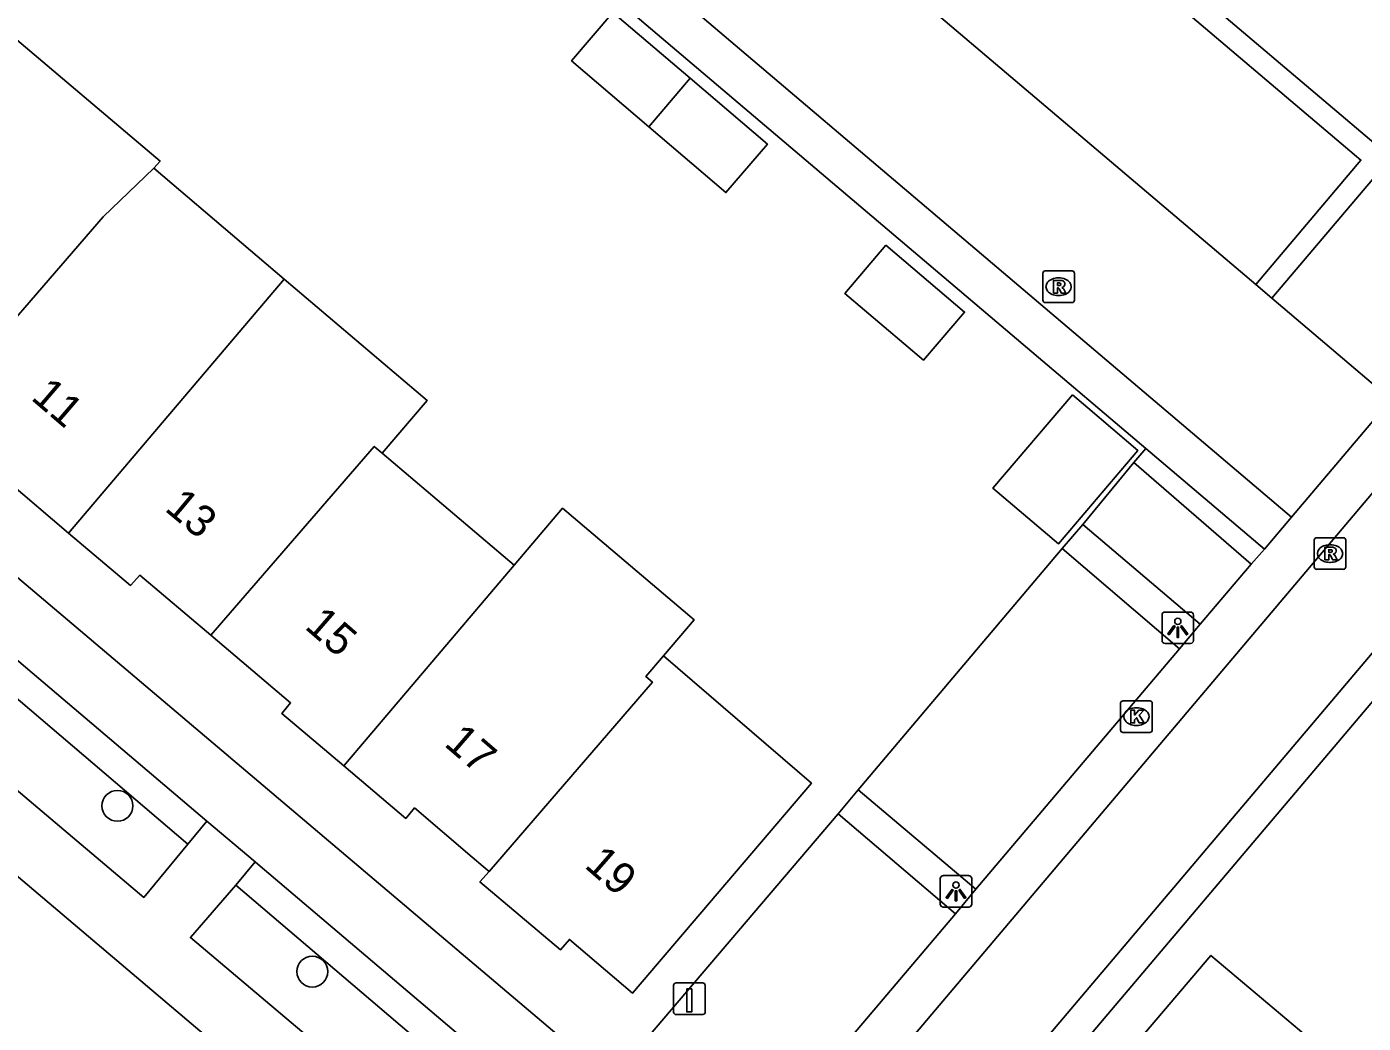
# Model space of a CAD drawing. Extents: x 156414 to 157775, y 382335 to 383765.
# Drawn here: x 156887.69 to 156930, y 382464.58 to 382496.14 of the extents above; entities that cross this region are included whole.
import ezdxf

# ---------------------------------------------------------------- set-up
doc = ezdxf.new("R2010")
doc.units = 0
for name, color, linetype in [('IMGEO_Boom', 7, 'Continuous'), ('IMGEO_Haag', 7, 'Continuous'), ('IMGEO_Kolk', 7, 'Continuous'), ('IMGEO_Laadpaal', 7, 'Continuous'), ('IMGEO_Lichtpunt', 7, 'Continuous'), ('IMGEO_Pand', 7, 'Continuous'), ('IMGEO_Pand_nummerreeks', 7, 'Continuous'), ('IMGEO_Parkeervlak_open', 7, 'Continuous'), ('IMGEO_Rijbaan_lokaal_halfverhard', 7, 'Continuous'), ('IMGEO_Rijbaan_lokaal_open', 7, 'Continuous'), ('IMGEO_Rioolput', 7, 'Continuous'), ('IMGEO_Voetpad_open', 7, 'Continuous')]:
    doc.layers.add(name, color=color, linetype=linetype)

msp = doc.modelspace()

# ---------------------------------------------------------------- linework, layer by layer
at = {"layer": 'IMGEO_Boom'}
for centre in [(156890.565, 382471.468), (156896.734, 382466.219)]:
    msp.add_circle(centre, 0.489, dxfattribs=at)
at = {"layer": 'IMGEO_Haag'}
for points in [[(156917.74, 382502.264), (156929.928, 382491.915), (156926.602, 382487.977)], [(156865.838, 382490.195), (156867.222, 382492.051), (156892.793, 382470.251)], [(156923.115, 382482.783), (156922.744, 382482.335)], [(156920.474, 382479.614), (156921.12, 382480.379)], [(156914.017, 382471.975), (156913.377, 382471.218)], [(156894.312, 382468.956), (156904.355, 382460.394), (156902.914, 382458.82)]]:
    msp.add_lwpolyline(points, dxfattribs=at)
at = {"layer": 'IMGEO_Kolk'}
for p, q in [((156922.32, 382473.867), (156922.32, 382474.719)), ((156922.395, 382474.793), (156923.247, 382474.793)), ((156922.808, 382474.573), (156922.833, 382474.573)), ((156923.321, 382474.719), (156923.321, 382473.867)), ((156923.247, 382473.793), (156922.395, 382473.793)), ((156922.831, 382474.013), (156922.806, 382474.013))]:
    msp.add_line(p, q, dxfattribs=at)
for points in [[(156922.32, 382473.867), (156922.32, 382474.719)], [(156922.395, 382474.793), (156923.247, 382474.793)], [(156923.321, 382474.719), (156923.321, 382473.867)], [(156922.641, 382474.493), (156922.764, 382474.493), (156922.764, 382474.342), (156922.894, 382474.493), (156923.058, 382474.493), (156922.912, 382474.342), (156923.065, 382474.093), (156922.913, 382474.093), (156922.828, 382474.257), (156922.764, 382474.19), (156922.764, 382474.093), (156922.641, 382474.093), (156922.641, 382474.493)], [(156923.247, 382473.793), (156922.395, 382473.793)]]:
    msp.add_lwpolyline(points, dxfattribs=at)
for centre, start, end in [((156922.397, 382474.717), 91.552, 178.448), ((156922.397, 382474.717), 91.552, 178.448), ((156923.245, 382474.717), 1.552, 88.448), ((156923.245, 382474.717), 1.552, 88.448), ((156922.397, 382473.869), 181.552, 268.448), ((156922.397, 382473.869), 181.552, 268.448), ((156923.245, 382473.869), 271.552, 358.448), ((156923.245, 382473.869), 271.552, 358.448)]:
    msp.add_arc(centre, 0.0765, start, end, dxfattribs=at)
for centre, major_axis, ratio, start_param, end_param in [((156922.807, 382474.293), (-0.387, 0.002), 0.722429, 4.712389, 7.853982), ((156922.832, 382474.293), (-0.39, 0.002), 0.717154, 1.570796, 4.712389)]:
    msp.add_ellipse(centre, major_axis=major_axis, ratio=ratio, start_param=start_param, end_param=end_param, dxfattribs=at)
at = {"layer": 'IMGEO_Laadpaal'}
for p, q in [((156908.172, 382465.775), (156908.172, 382464.934)), ((156908.172, 382465.775), (156908.172, 382464.934)), ((156909.088, 382465.859), (156908.247, 382465.859)), ((156909.088, 382465.859), (156908.247, 382465.859)), ((156909.172, 382464.943), (156909.172, 382465.784)), ((156909.172, 382464.943), (156909.172, 382465.784)), ((156908.256, 382464.859), (156909.097, 382464.859)), ((156908.256, 382464.859), (156909.097, 382464.859))]:
    msp.add_line(p, q, dxfattribs=at)
msp.add_lwpolyline([(156908.587, 382465.672), (156908.747, 382465.672), (156908.747, 382464.939), (156908.587, 382464.939), (156908.587, 382465.672)], dxfattribs=at)
for centre, start, end in [((156908.25, 382465.781), 92.4484, 184.2845), ((156908.25, 382465.781), 92.4484, 184.2845), ((156909.094, 382465.781), 2.4484, 94.2845), ((156909.094, 382465.781), 2.4484, 94.2845), ((156908.25, 382464.937), 182.4484, 274.2845), ((156908.25, 382464.937), 182.4484, 274.2845), ((156909.094, 382464.937), 272.4484, 4.2845), ((156909.094, 382464.937), 272.4484, 4.2845)]:
    msp.add_arc(centre, 0.0779, start, end, dxfattribs=at)
at = {"layer": 'IMGEO_Lichtpunt'}
for p, q in [((156923.633, 382477.509), (156923.633, 382476.702)), ((156923.633, 382477.509), (156923.633, 382476.702)), ((156924.535, 382477.604), (156923.727, 382477.604)), ((156924.535, 382477.604), (156923.727, 382477.604)), ((156924.629, 382476.702), (156924.629, 382477.509)), ((156924.629, 382476.702), (156924.629, 382477.509)), ((156923.727, 382476.608), (156924.535, 382476.608)), ((156923.727, 382476.608), (156924.535, 382476.608)), ((156916.611, 382469.161), (156916.611, 382468.354)), ((156916.611, 382469.161), (156916.611, 382468.354)), ((156917.513, 382469.256), (156916.705, 382469.256)), ((156917.513, 382469.256), (156916.705, 382469.256)), ((156917.607, 382468.354), (156917.607, 382469.161)), ((156917.607, 382468.354), (156917.607, 382469.161)), ((156916.705, 382468.26), (156917.513, 382468.26)), ((156916.705, 382468.26), (156917.513, 382468.26))]:
    msp.add_line(p, q, dxfattribs=at)
for points in [[(156924.007, 382477.173), (156924.046, 382477.145), (156923.858, 382476.883), (156923.82, 382476.91), (156924.007, 382477.173)], [(156924.109, 382477.125), (156924.156, 382477.125), (156924.156, 382476.803), (156924.109, 382476.803), (156924.109, 382477.125)], [(156924.219, 382477.145), (156924.257, 382477.172), (156924.444, 382476.91), (156924.405, 382476.882), (156924.219, 382477.145)], [(156916.985, 382468.825), (156917.024, 382468.797), (156916.836, 382468.535), (156916.798, 382468.562), (156916.985, 382468.825)], [(156917.087, 382468.777), (156917.134, 382468.777), (156917.134, 382468.455), (156917.087, 382468.455), (156917.087, 382468.777)], [(156917.197, 382468.797), (156917.235, 382468.824), (156917.422, 382468.562), (156917.383, 382468.534), (156917.197, 382468.797)]]:
    msp.add_lwpolyline(points, dxfattribs=at)
for centre in [(156924.132, 382477.307), (156917.11, 382468.959)]:
    msp.add_circle(centre, 0.0994, dxfattribs=at)
for centre, start, end in [((156923.727, 382477.509), 90, 180), ((156923.727, 382477.509), 90, 180), ((156924.535, 382477.509), 0, 90), ((156924.535, 382477.509), 0, 90), ((156923.727, 382476.702), 180, 270), ((156923.727, 382476.702), 180, 270), ((156924.535, 382476.702), 270, 0), ((156924.535, 382476.702), 270, 360), ((156916.705, 382469.161), 90, 180), ((156916.705, 382469.161), 90, 180), ((156917.513, 382469.161), 0, 90), ((156917.513, 382469.161), 0, 90), ((156916.705, 382468.354), 180, 270), ((156916.705, 382468.354), 180, 270), ((156917.513, 382468.354), 270, 0), ((156917.513, 382468.354), 270, 360)]:
    msp.add_arc(centre, 0.0946, start, end, dxfattribs=at)
at = {"layer": 'IMGEO_Pand'}
for points in [[(156907.385, 382492.974), (156904.941, 382495.062), (156906.25, 382496.595), (156908.694, 382494.507)], [(156885.573, 382493.956), (156887.239, 382495.838), (156891.913, 382491.884), (156891.713, 382491.658)], [(156908.694, 382494.507), (156911.138, 382492.42), (156909.829, 382490.887), (156907.385, 382492.974)], [(156907.385, 382492.974), (156908.694, 382494.507)], [(156891.713, 382491.658), (156890.113, 382490.118), (156884.943, 382484.14)], [(156891.713, 382491.658), (156895.841, 382488.151)], [(156914.894, 382489.224), (156917.381, 382487.106), (156916.078, 382485.576), (156913.591, 382487.694), (156914.894, 382489.224)], [(156889.019, 382480.107), (156895.841, 382488.151)], [(156895.841, 382488.151), (156900.374, 382484.301), (156898.946, 382482.636)], [(156920.8, 382484.482), (156921.286, 382484.068), (156922.87, 382482.719), (156920.35, 382479.761), (156918.281, 382481.523), (156920.8, 382484.482)], [(156889.019, 382480.107), (156887.065, 382481.767), (156887.352, 382482.097), (156884.943, 382484.14)], [(156898.946, 382482.636), (156898.692, 382482.852), (156893.52, 382476.87)], [(156898.946, 382482.636), (156903.127, 382479.091)], [(156903.127, 382479.091), (156904.654, 382480.89), (156908.822, 382477.357), (156907.846, 382476.217)], [(156893.52, 382476.87), (156891.279, 382478.772), (156890.975, 382478.448), (156889.019, 382480.107)], [(156903.127, 382479.091), (156897.73, 382472.734)], [(156897.73, 382472.734), (156895.764, 382474.396), (156896.048, 382474.727), (156893.52, 382476.87)], [(156907.846, 382476.217), (156912.534, 382472.181), (156906.871, 382465.535), (156904.871, 382467.239), (156904.59, 382466.906), (156902.042, 382469.056), (156902.328, 382469.388)], [(156902.328, 382469.388), (156907.501, 382475.382), (156907.287, 382475.564), (156907.846, 382476.217)], [(156902.328, 382469.388), (156902.144, 382469.545), (156901.796, 382469.842), (156899.971, 382471.402), (156899.692, 382471.067), (156897.73, 382472.734)], [(156924.679, 382458.447), (156920.866, 382461.651), (156925.178, 382466.731), (156928.981, 382463.515)]]:
    msp.add_lwpolyline(points, dxfattribs=at)
at = {"layer": 'IMGEO_Parkeervlak_open'}
for points in [[(156930.884, 382492.003), (156918.172, 382502.778)], [(156927.106, 382487.549), (156930.884, 382492.003)], [(156921.12, 382480.379), (156922.744, 382482.335)], [(156922.744, 382482.335), (156926.449, 382479.116)], [(156924.841, 382477.219), (156921.12, 382480.379)], [(156914.017, 382471.975), (156920.474, 382479.614)], [(156920.474, 382479.614), (156924.189, 382476.441)], [(156917.741, 382468.828), (156914.017, 382471.975)], [(156906.888, 382463.596), (156913.377, 382471.218)], [(156913.377, 382471.218), (156917.096, 382468.044)]]:
    msp.add_lwpolyline(points, dxfattribs=at)
at = {"layer": 'IMGEO_Rijbaan_lokaal_halfverhard'}
for points in [[(156927.729, 382480.609), (156906.502, 382498.639)], [(156914.409, 382498.327), (156926.602, 382487.977)], [(156926.602, 382487.977), (156927.106, 382487.549)], [(156930.887, 382484.34), (156927.106, 382487.549)], [(156927.729, 382480.609), (156930.887, 382484.34)]]:
    msp.add_lwpolyline(points, dxfattribs=at)
at = {"layer": 'IMGEO_Rijbaan_lokaal_open'}
for points in [[(156942.158, 382490.336), (156914.173, 382457.263)], [(156907.746, 382454.691), (156934.819, 382486.732)]]:
    msp.add_lwpolyline(points, dxfattribs=at)
at = {"layer": 'IMGEO_Rioolput'}
for p, q in [((156919.858, 382487.48), (156919.858, 382488.332)), ((156919.933, 382488.406), (156920.785, 382488.406)), ((156920.346, 382488.186), (156920.371, 382488.186)), ((156920.859, 382488.332), (156920.859, 382487.48)), ((156920.369, 382487.626), (156920.344, 382487.626)), ((156920.785, 382487.406), (156919.933, 382487.406)), ((156928.45, 382479.031), (156928.45, 382479.883)), ((156928.525, 382479.957), (156929.377, 382479.957)), ((156928.938, 382479.737), (156928.963, 382479.737)), ((156929.451, 382479.883), (156929.451, 382479.031)), ((156928.961, 382479.177), (156928.936, 382479.177)), ((156929.377, 382478.957), (156928.525, 382478.957))]:
    msp.add_line(p, q, dxfattribs=at)
for points in [[(156919.858, 382487.48), (156919.858, 382488.332)], [(156919.933, 382488.406), (156920.785, 382488.406)], [(156920.447, 382488.104), (156920.195, 382488.106), (156920.195, 382487.706)], [(156920.859, 382488.332), (156920.859, 382487.48)], [(156920.195, 382487.706), (156920.319, 382487.706), (156920.319, 382487.868), (156920.33, 382487.868)], [(156920.373, 382488.025), (156920.319, 382488.025), (156920.319, 382487.944)], [(156920.319, 382487.944), (156920.371, 382487.944)], [(156920.377, 382487.839), (156920.448, 382487.706), (156920.588, 382487.706), (156920.523, 382487.832)], [(156920.785, 382487.406), (156919.933, 382487.406)], [(156928.45, 382479.031), (156928.45, 382479.883)], [(156928.525, 382479.957), (156929.377, 382479.957)], [(156929.039, 382479.655), (156928.787, 382479.657), (156928.787, 382479.257)], [(156929.451, 382479.883), (156929.451, 382479.031)], [(156928.787, 382479.257), (156928.911, 382479.257), (156928.911, 382479.419), (156928.922, 382479.419)], [(156928.965, 382479.576), (156928.911, 382479.576), (156928.911, 382479.495)], [(156928.911, 382479.495), (156928.963, 382479.495)], [(156928.969, 382479.39), (156929.04, 382479.257), (156929.18, 382479.257), (156929.115, 382479.383)], [(156929.377, 382478.957), (156928.525, 382478.957)]]:
    msp.add_lwpolyline(points, dxfattribs=at)
for centre, radius, start, end in [((156919.935, 382488.33), 0.0765, 91.552, 178.448), ((156919.935, 382488.33), 0.0765, 91.552, 178.448), ((156920.446, 382487.994), 0.109, 350.3612, 89.416), ((156920.783, 382488.33), 0.0765, 1.552, 88.448), ((156920.783, 382488.33), 0.0765, 1.552, 88.448), ((156920.329, 382487.815), 0.0533, 26.0293, 88.6989), ((156920.355, 382488.133), 0.19, 274.7715, 282.9687), ((156920.379, 382487.929), 0.0964, 77.0061, 93.1865), ((156920.393, 382487.986), 0.0378, 276.6634, 79.6772), ((156920.444, 382487.994), 0.112, 277.5842, 350.9817), ((156920.428, 382487.779), 0.108, 29.5134, 73.7905), ((156919.935, 382487.482), 0.0765, 181.552, 268.448), ((156919.935, 382487.482), 0.0765, 181.552, 268.448), ((156920.783, 382487.482), 0.0765, 271.552, 358.448), ((156920.783, 382487.482), 0.0765, 271.552, 358.448), ((156928.527, 382479.881), 0.0765, 91.552, 178.448), ((156928.527, 382479.881), 0.0765, 91.552, 178.448), ((156929.038, 382479.545), 0.109, 350.3612, 89.416), ((156929.375, 382479.881), 0.0765, 1.552, 88.448), ((156929.375, 382479.881), 0.0765, 1.552, 88.448), ((156928.921, 382479.366), 0.0533, 26.0293, 88.6989), ((156928.947, 382479.684), 0.19, 274.7715, 282.9687), ((156928.971, 382479.48), 0.0964, 77.0061, 93.1865), ((156928.985, 382479.537), 0.0378, 276.6634, 79.6772), ((156929.036, 382479.545), 0.112, 277.5842, 350.9817), ((156929.02, 382479.33), 0.108, 29.5134, 73.7905), ((156928.527, 382479.033), 0.0765, 181.552, 268.448), ((156928.527, 382479.033), 0.0765, 181.552, 268.448), ((156929.375, 382479.033), 0.0765, 271.552, 358.448), ((156929.375, 382479.033), 0.0765, 271.552, 358.448)]:
    msp.add_arc(centre, radius, start, end, dxfattribs=at)
for centre, major_axis, ratio, start_param, end_param in [((156920.345, 382487.906), (-0.387, 0.002), 0.722429, 4.712389, 7.853982), ((156920.37, 382487.906), (-0.39, 0.002), 0.717154, 1.570796, 4.712389), ((156928.937, 382479.457), (-0.387, 0.002), 0.722429, 4.712389, 7.853982), ((156928.962, 382479.457), (-0.39, 0.002), 0.717154, 1.570796, 4.712389)]:
    msp.add_ellipse(centre, major_axis=major_axis, ratio=ratio, start_param=start_param, end_param=end_param, dxfattribs=at)
at = {"layer": 'IMGEO_Voetpad_open'}
for points in [[(156886.06, 382514.223), (156923.115, 382482.783)], [(156893.399, 382470.983), (156870.843, 382490.126), (156863.984, 382495.86)], [(156869.142, 382494.152), (156906.194, 382462.781)], [(156865.838, 382490.195), (156869.063, 382487.465), (156891.396, 382468.566), (156892.793, 382470.251)], [(156942.935, 382489.709), (156914.933, 382456.618)], [(156901.478, 382457.302), (156867.914, 382485.747), (156864.461, 382488.664)], [(156923.115, 382482.783), (156926.871, 382479.596)], [(156926.871, 382479.596), (156927.729, 382480.609)], [(156926.449, 382479.116), (156926.871, 382479.596)], [(156924.841, 382477.219), (156926.449, 382479.116)], [(156924.189, 382476.441), (156924.841, 382477.219)], [(156924.189, 382476.441), (156917.741, 382468.828)], [(156892.793, 382470.251), (156893.399, 382470.983)], [(156893.399, 382470.983), (156894.923, 382469.689)], [(156894.923, 382469.689), (156894.312, 382468.956)], [(156908.621, 382458.064), (156895.005, 382469.619), (156894.923, 382469.689)], [(156894.312, 382468.956), (156892.873, 382467.296), (156902.914, 382458.82)], [(156917.096, 382468.044), (156917.741, 382468.828)], [(156917.096, 382468.044), (156910.633, 382460.428)]]:
    msp.add_lwpolyline(points, dxfattribs=at)

# ---------------------------------------------------------------- texts
at = {"layer": 'IMGEO_Pand_nummerreeks'}
for s, rotation, p in [('11', 319.3544, (156887.794, 382484.357)), ('13', 320.1014, (156892.027, 382480.839)), ('15', 319.123, (156896.458, 382477.105)), ('17', 319.1939, (156900.873, 382473.392)), ('19', 318.833, (156905.314, 382469.54))]:
    msp.add_text(s, height=1, rotation=rotation, dxfattribs=at).set_placement(p)

doc.saveas('drawing.dxf')
